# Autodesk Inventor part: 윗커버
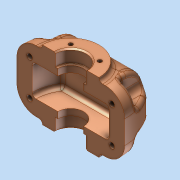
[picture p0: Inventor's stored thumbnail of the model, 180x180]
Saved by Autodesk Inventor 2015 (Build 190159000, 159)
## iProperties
Created: 2024-06
Part Number: 윗커버
Material: 일반
Document SubType Name: Modeling
Designer: Administrator
Density: 1 g/cm^3
Appearance: 기본값
Author: Administrator
Author: jhkim
Creation Date: 2024-05-29
Sending System: Autodesk Inventor 2025
Preprocessor: ST-DEVELOPER v20
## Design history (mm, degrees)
node "윗커버1"
node "솔리드1"
node "기준1"
